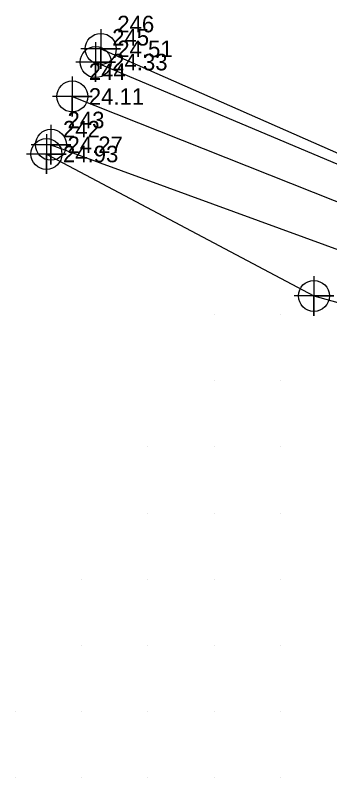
# Model space of a CAD drawing. Extents: x 2204340 to 2204783, y 268170 to 268760.
# Drawn here: x 2204430 to 2204477.4, y 268408.1 to 268525.2 of the extents above; entities that cross this region are included whole.
import ezdxf

# ---------------------------------------------------------------- set-up
doc = ezdxf.new("R2010")
doc.units = 0
for name, color, linetype in [('Exist DTM Breakline', 7, 'Continuous'), ('Exist DTM Breakline Cogo Elevation', 7, 'Continuous'), ('Exist DTM Breakline Cogo Number', 7, 'Continuous'), ('Exist DTM Breakline Cogo Point CELL', 7, 'Continuous'), ('Exist DTM Breakline Underwater', 7, 'Continuous'), ('Exist DTM Breakline Underwater Cogo Elevation', 7, 'Continuous'), ('Exist DTM Breakline Underwater Cogo Number', 7, 'Continuous'), ('Exist DTM Breakline Underwater Cogo Point CELL', 7, 'Continuous'), ('Exist DTM QL2 LIDAR Elevation Point', 7, 'Continuous'), ('Exist Hydro Jurisdictional Stream or Body of Water', 7, 'Continuous')]:
    doc.layers.add(name, color=color, linetype=linetype)

msp = doc.modelspace()

# ---------------------------------------------------------------- linework, layer by layer
at = {"layer": 'Exist DTM Breakline'}
for points in [[(2204442.11, 268518.11), (2204480.82, 268501.8), (2204502.53, 268495.78), (2204515.27, 268483.58), (2204555.41, 268455.78), (2204577.65, 268446.31), (2204630.94, 268427.72)], [(2204435.36, 268505.62), (2204480.45, 268489.14), (2204494.51, 268488.53), (2204511.37, 268475.79), (2204547.35, 268444.74), (2204573.73, 268433.57), (2204620.13, 268409.58)]]:
    msp.add_lwpolyline(points, dxfattribs=at)
at = {"layer": 'Exist DTM Breakline Cogo Point CELL'}
for points in [[(2204442.88, 268523.11), (2204442.88, 268517.11), (2204442.88, 268520.11), (2204445.88, 268520.11), (2204439.88, 268520.11)], [(2204442.11, 268521.11), (2204442.11, 268515.11), (2204442.11, 268518.11), (2204445.11, 268518.11), (2204439.11, 268518.11)], [(2204435.36, 268508.62), (2204435.36, 268502.62), (2204435.36, 268505.62), (2204438.36, 268505.62), (2204432.36, 268505.62)], [(2204434.67, 268507.23), (2204434.67, 268501.23), (2204434.67, 268504.23), (2204437.67, 268504.23), (2204431.67, 268504.23)], [(2204475.09, 268485.79), (2204475.09, 268479.79), (2204475.09, 268482.79), (2204478.09, 268482.79), (2204472.09, 268482.79)]]:
    msp.add_lwpolyline(points, dxfattribs=at)
for centre in [(2204442.88, 268520.11), (2204442.11, 268518.11), (2204435.36, 268505.62), (2204434.67, 268504.23), (2204475.09, 268482.79)]:
    msp.add_circle(centre, 2.34, dxfattribs=at)
at = {"layer": 'Exist DTM Breakline Underwater'}
msp.add_lwpolyline([(2204438.58, 268512.92), (2204481.57, 268495.84), (2204497.2, 268490.9), (2204514.25, 268479.67), (2204552.14, 268449.92), (2204576, 268440.35), (2204624.81, 268416.78)], dxfattribs=at)
at = {"layer": 'Exist DTM Breakline Underwater Cogo Point CELL'}
msp.add_lwpolyline([(2204438.58, 268515.92), (2204438.58, 268509.92), (2204438.58, 268512.92), (2204441.58, 268512.92), (2204435.58, 268512.92)], dxfattribs=at)
msp.add_circle((2204438.58, 268512.92), 2.34, dxfattribs=at)
at = {"layer": 'Exist DTM QL2 LIDAR Elevation Point'}
for p, q in [((2204460, 268480), (2204460, 268480)), ((2204470, 268480), (2204470, 268480)), ((2204460, 268470), (2204460, 268470)), ((2204470, 268470), (2204470, 268470)), ((2204450, 268460), (2204450, 268460)), ((2204460, 268460), (2204460, 268460)), ((2204470, 268460), (2204470, 268460)), ((2204450, 268450), (2204450, 268450)), ((2204460, 268450), (2204460, 268450)), ((2204470, 268450), (2204470, 268450)), ((2204440, 268440), (2204440, 268440)), ((2204450, 268440), (2204450, 268440)), ((2204460, 268440), (2204460, 268440)), ((2204470, 268440), (2204470, 268440)), ((2204440, 268430), (2204440, 268430)), ((2204450, 268430), (2204450, 268430)), ((2204460, 268430), (2204460, 268430)), ((2204470, 268430), (2204470, 268430)), ((2204430, 268420), (2204430, 268420)), ((2204440, 268420), (2204440, 268420)), ((2204450, 268420), (2204450, 268420)), ((2204460, 268420), (2204460, 268420)), ((2204470, 268420), (2204470, 268420)), ((2204430, 268410), (2204430, 268410)), ((2204440, 268410), (2204440, 268410)), ((2204450, 268410), (2204450, 268410)), ((2204460, 268410), (2204460, 268410)), ((2204470, 268410), (2204470, 268410))]:
    msp.add_line(p, q, dxfattribs=at)
at = {"layer": 'Exist Hydro Jurisdictional Stream or Body of Water'}
for points in [[(2204442.88, 268520.11), (2204480.52, 268503.56), (2204503.23, 268495.9), (2204516.01, 268483.84), (2204556.67, 268458.09), (2204576.77, 268447.29), (2204631.19, 268429.04)], [(2204434.67, 268504.23), (2204475.09, 268482.79), (2204492.09, 268478.07), (2204511.02, 268474.48), (2204547.96, 268443.09), (2204571.96, 268432.88), (2204619.17, 268408.09)]]:
    msp.add_lwpolyline(points, dxfattribs=at)

# ---------------------------------------------------------------- texts
at = {"layer": 'Exist DTM Breakline Cogo Elevation'}
for s, p in [('24.51', (2204445.38, 268518.86)), ('24.33', (2204444.61, 268516.86)), ('24.27', (2204437.86, 268504.37)), ('24.93', (2204437.17, 268502.98))]:
    msp.add_text(s, height=2.5, dxfattribs=at).set_placement(p)
at = {"layer": 'Exist DTM Breakline Cogo Number'}
for s, p in [('246', (2204445.38, 268522.61)), ('245', (2204444.61, 268520.61)), ('243', (2204437.86, 268508.12)), ('242', (2204437.17, 268506.73))]:
    msp.add_text(s, height=2.5, dxfattribs=at).set_placement(p)
at = {"layer": 'Exist DTM Breakline Underwater Cogo Elevation'}
msp.add_text('24.11', height=2.5, dxfattribs=at).set_placement((2204441.08, 268511.67))
at = {"layer": 'Exist DTM Breakline Underwater Cogo Number'}
msp.add_text('244', height=2.5, dxfattribs=at).set_placement((2204441.08, 268515.42))

doc.saveas('drawing.dxf')
